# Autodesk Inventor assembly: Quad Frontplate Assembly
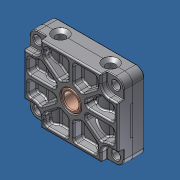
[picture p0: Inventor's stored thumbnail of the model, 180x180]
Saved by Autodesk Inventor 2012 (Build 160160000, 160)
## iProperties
Created: 2013-10
Part Number: Quad Frontplate Assembly
Document SubType Name: Assembly
Designer: Admin
Author: Admin
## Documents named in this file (3)
- C:\Andys Backup Data\ANDY'S INVENTOR\INVENTOR LIBRARIES\PARTS LIBRARY\HYDRAULIC VERTICAL ADJUSTMENT\27.9001Telescoping Twin Leg System\SUBCOMPONENTS\Qxx18_crank pump\Quad Frontplate Assembly.iam
- C:\Andys Backup Data\ANDY'S INVENTOR\INVENTOR LIBRARIES\PARTS LIBRARY\HYDRAULIC VERTICAL ADJUSTMENT\27.9001Telescoping Twin Leg System\SUBCOMPONENTS\Qxx18_crank pump\655-01002 Quad Frontplate Bushing.ipt
- C:\Andys Backup Data\ANDY'S INVENTOR\INVENTOR LIBRARIES\PARTS LIBRARY\HYDRAULIC VERTICAL ADJUSTMENT\27.9001Telescoping Twin Leg System\SUBCOMPONENTS\Qxx18_crank pump\665-02103 Quad Frontplate.ipt
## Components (2 placed, 2 different names)
1. 655-01002 Quad Frontplate Bushing:1
2. 665-02103 Quad Frontplate:1
